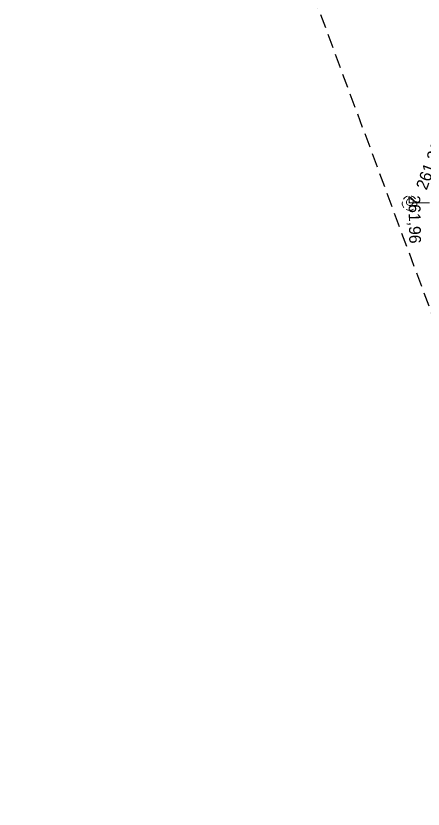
# Model space of a CAD drawing. Extents: x -732074 to -731966, y -1048695 to -1047982.
# Drawn here: x -732069.3 to -732041.6, y -1048122.1 to -1048068.3 of the extents above; entities that cross this region are included whole.
import ezdxf

# ---------------------------------------------------------------- set-up
doc = ezdxf.new("R2010")
doc.units = 0
doc.header["$LTSCALE"] = 0.32
doc.linetypes.add('MEDIUM_DASHED', pattern=[4.5, 3, -1.5])
doc.layers.add('1', color=7, linetype='Continuous')
for name, color, linetype, lineweight in [('18', 7, 'Continuous', 13), ('49', 7, 'Continuous', 13), ('63', 7, 'MEDIUM_DASHED', 25)]:
    doc.layers.add(name, color=color, linetype=linetype, lineweight=lineweight)

msp = doc.modelspace()

# ---------------------------------------------------------------- linework, layer by layer
at = {"layer": '18'}
for points in [[(-732042.692, -1048080.507), (-732042.763, -1048080.535), (-732042.83, -1048080.574), (-732042.89, -1048080.622), (-732042.941, -1048080.679), (-732042.965, -1048080.713)], [(-732042.151, -1048080.69), (-732042.201, -1048080.632), (-732042.259, -1048080.582), (-732042.324, -1048080.541), (-732042.395, -1048080.512), (-732042.444, -1048080.498)], [(-732043.037, -1048080.899), (-732043.043, -1048080.976), (-732043.038, -1048081.053), (-732043.021, -1048081.128), (-732042.992, -1048081.199), (-732042.951, -1048081.265), (-732042.936, -1048081.287)], [(-732042.156, -1048081.276), (-732042.115, -1048081.211), (-732042.084, -1048081.141), (-732042.065, -1048081.066), (-732042.057, -1048080.99), (-732042.062, -1048080.913), (-732042.068, -1048080.878)], [(-732042.779, -1048081.416), (-732042.709, -1048081.447), (-732042.634, -1048081.466), (-732042.558, -1048081.473), (-732042.481, -1048081.468), (-732042.406, -1048081.451), (-732042.334, -1048081.423), (-732042.274, -1048081.388)]]:
    msp.add_lwpolyline(points, dxfattribs=at)
msp.add_lwpolyline([(-732042.299, -1048080.909), (-732042.305, -1048080.857), (-732042.323, -1048080.807), (-732042.351, -1048080.763), (-732042.389, -1048080.726), (-732042.434, -1048080.699), (-732042.484, -1048080.683), (-732042.536, -1048080.678), (-732042.588, -1048080.685), (-732042.637, -1048080.704), (-732042.681, -1048080.734), (-732042.716, -1048080.773), (-732042.742, -1048080.818), (-732042.757, -1048080.869), (-732042.76, -1048080.921), (-732042.752, -1048080.973), (-732042.731, -1048081.021), (-732042.701, -1048081.064), (-732042.661, -1048081.099), (-732042.615, -1048081.123), (-732042.564, -1048081.137), (-732042.512, -1048081.139), (-732042.46, -1048081.129), (-732042.412, -1048081.107), (-732042.37, -1048081.075), (-732042.337, -1048081.035), (-732042.313, -1048080.988), (-732042.301, -1048080.937)], close=True, dxfattribs=at)
at = {"layer": '49'}
msp.add_line((-732042.539, -1048080.97), (-732041.199, -1048080.95), dxfattribs=at)
msp.add_line((-732042.539, -1048080.97), (-732041.199, -1048080.95), dxfattribs=at)
at = {"layer": '63'}
msp.add_lwpolyline([(-732069.268, -1048320.571), (-732031.703, -1048203.502), (-732026.193, -1048128.486), (-732054.591, -1048051.968)], dxfattribs=at)

# ---------------------------------------------------------------- texts
at = {"layer": '1'}
for s, rotation, p in [('261,31', 70, (-732041.388, -1048080.138)), ('261,96', 271, (-732042.623, -1048080.461))]:
    msp.add_text(s, height=0.8, rotation=rotation, dxfattribs=at).set_placement(p)

doc.saveas('drawing.dxf')
